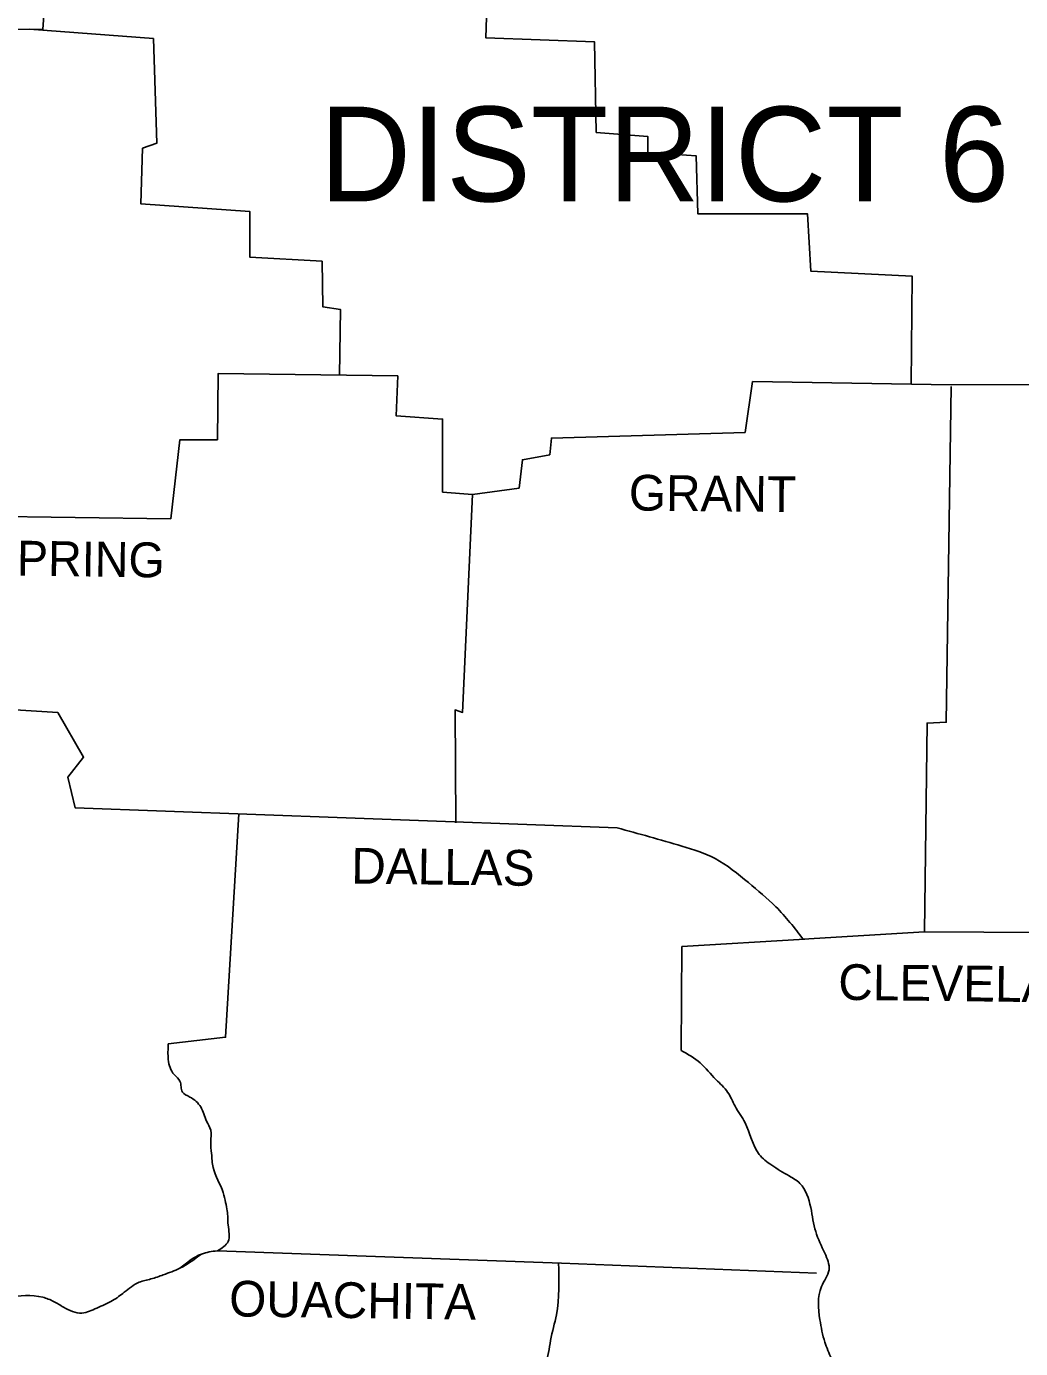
# Model space of a CAD drawing. Extents: x 3046 to 131673, y -8885 to 10756.
# Drawn here: x 65611 to 66781, y 6157 to 7714 of the extents above; entities that cross this region are included whole.
import ezdxf

# ---------------------------------------------------------------- set-up
doc = ezdxf.new("R2010")
doc.units = 0
for name, color, linetype in [('1', 7, 'Continuous'), ('2', 7, 'Continuous'), ('3', 7, 'Continuous')]:
    doc.layers.add(name, color=color, linetype=linetype)

msp = doc.modelspace()

# ---------------------------------------------------------------- linework, layer by layer
at = {"layer": '1'}
for points in [[(65958.7345219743, 7826.856547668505), (65638.79549273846, 7836.640615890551), (65629.98983146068, 7710.426136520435), (65238.62710437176, 7712.382950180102), (65236.67029075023, 7670.3114568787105)], [(66038.96388110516, 7830.219821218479), (66155.39429225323, 7822.942920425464), (66151.48066497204, 7700.642068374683), (66279.65195815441, 7695.7500342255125), (66281.60877173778, 7589.103690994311), (66342.26999434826, 7584.211657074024), (66342.26999434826, 7565.621927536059), (66399.01758983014, 7561.708300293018), (66400.97440345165, 7493.219822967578), (66530.12410331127, 7493.219822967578), (66534.03773059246, 7425.709752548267), (66653.40336230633, 7419.83931172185), (66652.42347569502, 7292.454043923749)], [(65614.37261814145, 7710.504222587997), (65760.11793807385, 7699.663661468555), (65764.03156531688, 7576.384402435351), (65747.39864947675, 7570.5139616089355), (65745.44183589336, 7504.960704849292), (65873.61312884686, 7496.155043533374), (65873.61312884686, 7442.34266857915), (65958.7345219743, 7437.45063442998), (65959.71292888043, 7383.638259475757), (65980.25947196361, 7380.703038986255), (65979.21460193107, 7303.382645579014)], [(67819.66428866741, 7405.163209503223), (67449.82651156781, 7414.947277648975), (67447.86969794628, 7294.603239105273), (66699.38848269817, 7291.668018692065)], [(65217.166960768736, 7142.025605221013), (65780.66448115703, 7134.144520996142), (65791.42695624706, 7227.093168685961), (65835.45526301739, 7227.093168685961), (65836.43366992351, 7305.365714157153), (66047.76954234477, 7302.430493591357), (66045.8127287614, 7255.466966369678), (66100.6035105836, 7251.5533390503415), (66100.6035105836, 7165.45353916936), (66135.82615588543, 7162.518318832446)], [(66135.82615588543, 7162.518318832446), (66190.61693770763, 7170.345573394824), (66194.53056498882, 7203.611405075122), (66226.81798991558, 7209.481845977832), (66228.7748035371, 7229.049982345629), (66456.7435920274, 7235.898830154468), (66465.54925330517, 7295.581646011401), (66699.38848269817, 7291.668018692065)], [(66699.38848269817, 7289.711205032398), (66693.51804175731, 6894.434850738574), (66671.0146850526, 6893.456443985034), (66668.07946463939, 6647.876332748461)], [(66135.82615588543, 7162.518318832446), (66124.08527408, 6906.175732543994), (66115.27961280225, 6909.11095310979), (66116.25801967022, 6776.047625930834)], [(65105.5637771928, 6880.7371554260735), (65103.606963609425, 6934.549530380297), (65119.26147265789, 6935.527937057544), (65129.04554087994, 7061.742416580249), (65279.720190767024, 7051.958348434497), (65275.806563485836, 6974.664209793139), (65470.50952014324, 6963.901734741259), (65471.48792704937, 6916.938207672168), (65647.60115401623, 6906.175732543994), (65677.9317655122, 6853.341764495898), (65659.3420358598, 6829.860000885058), (65668.14769729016, 6793.658948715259), (66306.06894214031, 6770.177185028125)], [(65860.58699415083, 6786.575293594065), (65845.23933120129, 6523.618667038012), (65777.72926078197, 6515.791412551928)], [(66527.18888293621, 6639.070671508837), (66382.38467398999, 6630.265010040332), (66381.40626708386, 6507.964157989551)], [(66668.07946463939, 6647.876332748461), (66525.23206935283, 6639.070671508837)], [(66668.07946463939, 6647.876332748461), (67016.39229155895, 6645.919519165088)], [(65835.45526301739, 6272.168114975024), (66240.51568538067, 6257.492012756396), (66540.88657824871, 6245.751130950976)]]:
    msp.add_lwpolyline(points, dxfattribs=at)
for points in [[(66306.06894214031, 6770.177185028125), (66382.38467398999, 6748.652235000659), (66421.52094653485, 6733.976132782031), (66460.65721927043, 6705.602335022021), (66492.94464423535, 6677.228537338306), (66525.23206935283, 6639.070671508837)], [(65777.72926078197, 6515.791412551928), (65777.72926078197, 6497.201682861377), (65784.57810847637, 6479.590360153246), (65791.42695624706, 6471.763105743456), (65794.36217662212, 6459.0438170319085), (65803.16783805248, 6453.173376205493), (65815.88712661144, 6441.432494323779), (65822.73597445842, 6424.799578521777), (65827.62800849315, 6414.0371033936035), (65827.62800849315, 6400.339408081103), (65828.60641539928, 6386.641712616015), (65830.56322898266, 6370.008796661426), (65842.3041106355, 6340.656592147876), (65845.23933120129, 6328.915710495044), (65847.19614482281, 6319.131642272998), (65848.17455157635, 6302.4987263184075), (65848.17455157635, 6282.930589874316), (65835.45526301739, 6272.168114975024)], [(66381.40626708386, 6507.964157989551), (66403.90962378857, 6493.2880556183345), (66422.49935344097, 6473.719919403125), (66436.19704890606, 6459.0438170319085), (66445.00271018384, 6442.410901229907), (66456.7435920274, 6422.842764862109), (66473.3765078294, 6385.663305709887), (66488.05261020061, 6372.944017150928), (66508.59915332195, 6360.22472843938), (66521.31844207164, 6351.419067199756), (66534.03773059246, 6323.04526951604), (66539.90817149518, 6294.671471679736), (66550.67064643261, 6269.23289463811), (66555.56268058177, 6249.664758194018), (66546.75701915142, 6230.096621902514), (66544.8002055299, 6190.960349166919), (66550.67064643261, 6164.543365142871), (66558.49790099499, 6144.975228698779), (66563.3899351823, 6122.471871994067), (66560.45471461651, 6115.623024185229)], [(65816.86553351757, 6268.254487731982), (65791.42695624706, 6251.621571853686), (65771.85881991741, 6243.794317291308), (65757.18271769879, 6238.902283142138), (65743.4850222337, 6234.988655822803), (65725.87369948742, 6223.247774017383), (65712.17600406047, 6213.463705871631), (65693.58627456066, 6204.658044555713), (65675.97495185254, 6198.787603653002), (65654.45000182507, 6205.636451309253), (65642.70912001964, 6212.485299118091), (65629.98983146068, 6217.377333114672), (65588.89674506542, 6217.377333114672)], [(65791.42695624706, 6251.621571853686), (65816.86553351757, 6268.254487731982), (65835.45526301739, 6272.168114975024)], [(66237.08427846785, 6257.806639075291), (66234.64524447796, 6196.830789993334), (66227.79639682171, 6166.5001787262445), (66220.94754901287, 6139.104787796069), (66206.27144683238, 6123.450278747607), (66190.61693770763, 6107.795769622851), (66175.94083552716, 6090.184446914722), (66163.2215468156, 6068.659496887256), (66150.50225825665, 6054.961801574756), (66133.86934222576, 6041.264106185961), (66117.23642638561, 6031.4800379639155), (66098.6466969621, 6022.67437649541), (66078.10015365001, 6017.782342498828), (66063.42405146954, 6007.019867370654), (66062.44564456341, 5983.538103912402), (66079.07856055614, 5950.272272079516), (66084.949001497, 5934.61776295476), (66086.90581515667, 5916.028033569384), (66080.05696730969, 5905.2655584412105), (66064.40245818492, 5896.459897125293), (66045.8127287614, 5885.697422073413), (66029.17981292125, 5875.913353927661), (66017.43893111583, 5859.280438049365), (66015.48211745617, 5836.777081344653), (66023.3093719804, 5810.360097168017), (66026.24459235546, 5794.705588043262), (66038.96388110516, 5770.245417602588), (66048.7479492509, 5771.223824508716), (66066.3592718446, 5770.245417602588), (66068.31608550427, 5765.3533836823), (66069.2944924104, 5760.461349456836), (66073.20811969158, 5747.7420608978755), (66087.88422187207, 5736.979585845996), (66089.84103549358, 5727.19551762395), (66098.6466969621, 5708.60578816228), (66113.32279914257, 5695.88649960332), (66124.08527408, 5691.972872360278), (66146.58863097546, 5685.12402455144), (66158.32951278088, 5682.188804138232), (66171.04880133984, 5653.815006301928), (66186.70331042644, 5654.793413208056), (66198.44419223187, 5656.750226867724), (66218.01232863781, 5651.858192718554), (66226.81798991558, 5640.117311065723), (66235.62365138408, 5620.54917462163), (66247.36453318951, 5606.851479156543), (66255.19178771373, 5606.851479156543)]]:
    msp.add_spline(points, degree=3, dxfattribs=at)

# ---------------------------------------------------------------- texts
at = {"layer": '2'}
for s, height, rotation, p in [('GRANT', 42.07344995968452, 359.4031917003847, (66319.7666376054, 7143.928589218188)), ('HOT SPRING', 41.09308632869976, 359.22157224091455, (65431.373247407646, 7069.569671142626)), ('DALLAS', 42.06170907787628, 359.2461527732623, (65992.97876052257, 6704.623928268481)), ('CLEVELAND', 42.07344995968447, 359.33765002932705, (66566.32515555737, 6567.646973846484)), ('OUACHITA', 42.07344995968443, 359.2042777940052, (65849.15295848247, 6194.873976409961))]:
    msp.add_text(s, height=height, rotation=rotation, dxfattribs=at).set_placement(p)
at = {"layer": '3'}
msp.add_text('DISTRICT 6', height=111.53837717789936, dxfattribs=at).set_placement((65955.79930159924, 7507.895925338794))

doc.saveas('drawing.dxf')
